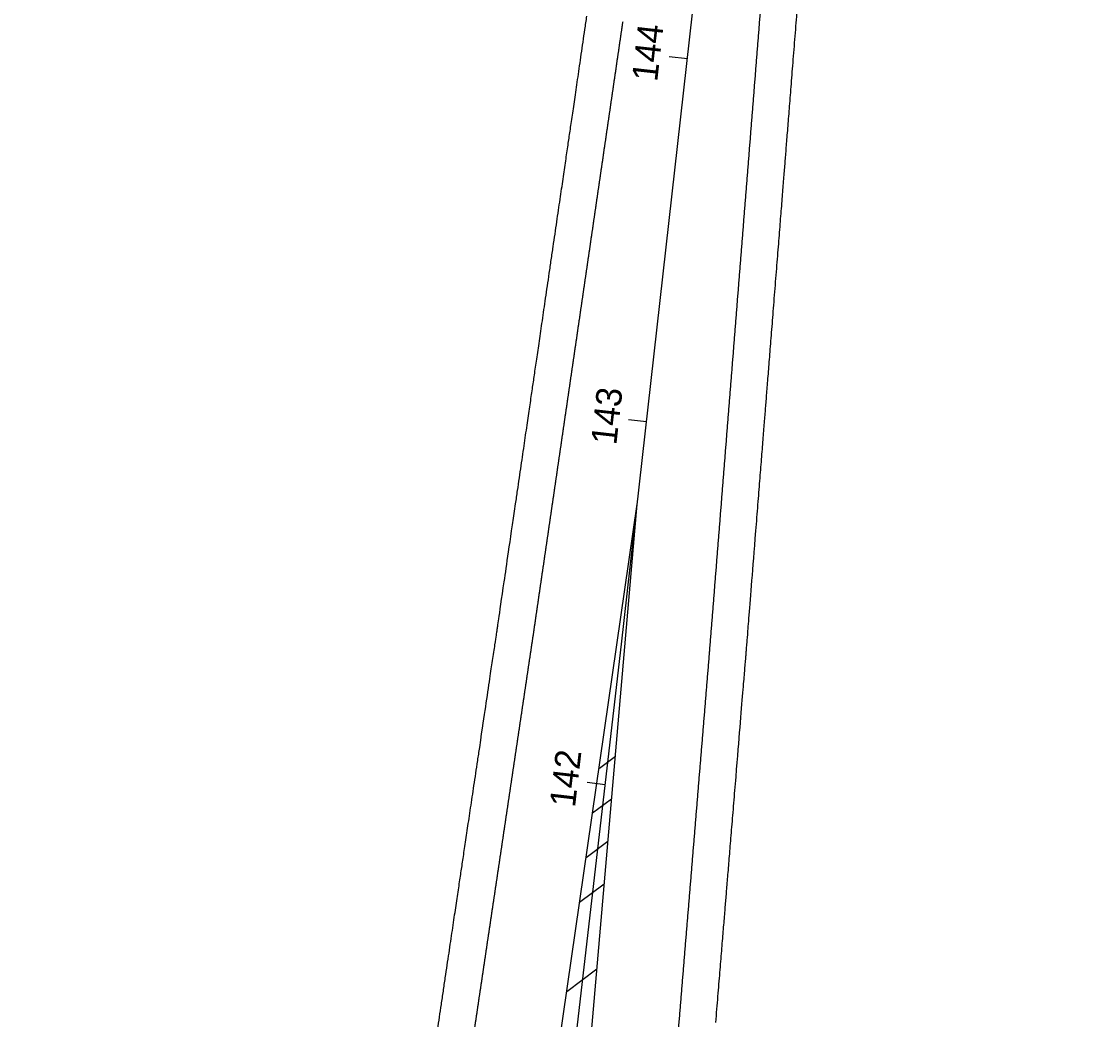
# Model space of a CAD drawing. Extents: x 2318076 to 2324211, y 613525 to 629939.
# Drawn here: x 2320485.2 to 2320778.2, y 628702.1 to 628975.4 of the extents above; entities that cross this region are included whole.
import ezdxf

# ---------------------------------------------------------------- set-up
doc = ezdxf.new("R2010")
doc.units = 0
for name, color, linetype in [('GE_P_CL_50', 7, 'Continuous'), ('PM_P_CL_Double_Solid', 7, 'Continuous'), ('PM_P_Transverse_Line', 7, 'Continuous'), ('PV_P_EOP', 7, 'Continuous'), ('PV_P_Shoulder', 7, 'Continuous')]:
    doc.layers.add(name, color=color, linetype=linetype)

msp = doc.modelspace()

# ---------------------------------------------------------------- linework, layer by layer
at = {"layer": 'GE_P_CL_50'}
for p, q in [((2320667.58, 628965.13), (2320662.61, 628965.69)), ((2320656.38, 628865.76), (2320651.41, 628866.32)), ((2320645.08, 628766.4), (2320640.11, 628766.97))]:
    msp.add_line(p, q, dxfattribs=at)
msp.add_lwpolyline([(2320485.22, 627375.57), (2320502.11, 627520.92), (2320519.22, 627676.47), (2320531.82, 627783.89), (2320546.8, 627927.12), (2320554.45, 627991.34), (2320572.51, 628138.41), (2320649.52, 628804.84), (2320678.77, 629064.5), (2320690.76, 629163.78), (2320713.75, 629362.45), (2320725.26, 629461.78), (2320736.97, 629561.09), (2320748.4, 629660.43), (2320759.09, 629759.86), (2320769.62, 629859.3), (2320777.51, 629931.12), (2320778.25, 629937.84)], dxfattribs=at)
at = {"layer": 'PM_P_CL_Double_Solid'}
for p in [(2320623.21, 628631.42), (2320635.3, 628629.45)]:
    msp.add_line(p, (2320653.84, 628843.21), dxfattribs=at)
at = {"layer": 'PM_P_Transverse_Line'}
for p, q in [((2320647.85, 628774.12), (2320643.47, 628770.85)), ((2320646.84, 628762.47), (2320641.6, 628758.56)), ((2320645.83, 628750.83), (2320639.83, 628746.35)), ((2320644.82, 628739.18), (2320638.07, 628734.13)), ((2320642.8, 628715.89), (2320634.53, 628709.71))]:
    msp.add_line(p, q, dxfattribs=at)
at = {"layer": 'PV_P_EOP'}
for points in [[(2320687.04, 628971.2), (2320687.12, 628972.11), (2320687.19, 628973.02), (2320687.26, 628973.93), (2320687.33, 628974.84), (2320687.4, 628975.75), (2320687.48, 628976.66), (2320687.55, 628977.57), (2320687.62, 628978.48), (2320687.69, 628979.38), (2320687.77, 628980.29), (2320687.84, 628981.2), (2320687.91, 628982.11), (2320687.98, 628983.02), (2320688.05, 628983.93), (2320688.13, 628984.84), (2320688.2, 628985.75), (2320688.27, 628986.66), (2320688.34, 628987.57), (2320688.42, 628988.47), (2320688.49, 628989.38), (2320688.56, 628990.29), (2320688.63, 628991.2), (2320688.7, 628992.11), (2320688.78, 628993.02), (2320688.85, 628993.93), (2320688.92, 628994.84), (2320688.99, 628995.75), (2320689.07, 628996.66), (2320689.14, 628997.57), (2320689.21, 628998.47), (2320689.28, 628999.38), (2320689.35, 629000.29), (2320689.43, 629001.2), (2320689.5, 629002.11), (2320689.57, 629003.02), (2320689.64, 629003.93), (2320689.71, 629004.84), (2320689.79, 629005.75), (2320689.86, 629006.66), (2320689.93, 629007.56), (2320690, 629008.47), (2320690.08, 629009.38), (2320690.15, 629010.29), (2320690.22, 629011.2), (2320690.29, 629012.11), (2320690.36, 629013.02), (2320690.44, 629013.93), (2320690.51, 629014.84), (2320690.58, 629015.75), (2320690.65, 629016.65), (2320690.73, 629017.56), (2320690.8, 629018.47), (2320690.87, 629019.38), (2320690.94, 629020.29), (2320691.01, 629021.2), (2320691.09, 629022.11), (2320691.16, 629023.02), (2320691.23, 629023.93), (2320691.3, 629024.84), (2320691.37, 629025.75), (2320691.45, 629026.65), (2320691.52, 629027.56), (2320691.59, 629028.47), (2320691.66, 629029.38), (2320691.74, 629030.29), (2320691.81, 629031.2), (2320691.88, 629032.11), (2320691.95, 629033.02), (2320692.02, 629033.93), (2320692.1, 629034.84), (2320692.17, 629035.74), (2320692.24, 629036.65), (2320692.31, 629037.56), (2320692.39, 629038.47)], [(2320640.19, 628908.61), (2320640.32, 628909.51), (2320640.45, 628910.41), (2320640.58, 628911.32), (2320640.72, 628912.22), (2320640.85, 628913.12), (2320640.98, 628914.02), (2320641.11, 628914.93), (2320641.24, 628915.83), (2320641.37, 628916.73), (2320641.51, 628917.63), (2320641.64, 628918.54), (2320641.77, 628919.44), (2320641.9, 628920.34), (2320642.03, 628921.24), (2320642.17, 628922.14), (2320642.3, 628923.05), (2320642.43, 628923.95), (2320642.56, 628924.85), (2320642.69, 628925.75), (2320642.82, 628926.66), (2320642.96, 628927.56), (2320643.09, 628928.46), (2320643.22, 628929.36), (2320643.35, 628930.27), (2320643.48, 628931.17), (2320643.62, 628932.07), (2320643.75, 628932.97), (2320643.88, 628933.87), (2320644.01, 628934.78), (2320644.14, 628935.68), (2320644.28, 628936.58), (2320644.41, 628937.48), (2320644.54, 628938.39), (2320644.67, 628939.29), (2320644.8, 628940.19), (2320644.93, 628941.09), (2320645.07, 628942), (2320645.2, 628942.9), (2320645.33, 628943.8), (2320645.46, 628944.7), (2320645.59, 628945.6), (2320645.73, 628946.51), (2320645.86, 628947.41), (2320645.99, 628948.31), (2320646.12, 628949.21), (2320646.25, 628950.12), (2320646.39, 628951.02), (2320646.52, 628951.92), (2320646.65, 628952.82), (2320646.78, 628953.73), (2320646.91, 628954.63), (2320647.04, 628955.53), (2320647.18, 628956.43), (2320647.31, 628957.34), (2320647.44, 628958.24), (2320647.57, 628959.14), (2320647.7, 628960.04), (2320647.84, 628960.94), (2320647.97, 628961.85), (2320648.1, 628962.75), (2320648.23, 628963.65), (2320648.36, 628964.55), (2320648.49, 628965.46), (2320648.63, 628966.36), (2320648.76, 628967.26), (2320648.89, 628968.16), (2320649.02, 628969.07), (2320649.15, 628969.97), (2320649.29, 628970.87), (2320649.42, 628971.77), (2320649.55, 628972.67), (2320649.68, 628973.58), (2320649.81, 628974.48), (2320649.95, 628975.38)], [(2320681.7, 628903.93), (2320681.78, 628904.84), (2320681.85, 628905.75), (2320681.92, 628906.66), (2320681.99, 628907.57), (2320682.06, 628908.48), (2320682.14, 628909.39), (2320682.21, 628910.3), (2320682.28, 628911.21), (2320682.35, 628912.11), (2320682.42, 628913.02), (2320682.5, 628913.93), (2320682.57, 628914.84), (2320682.64, 628915.75), (2320682.71, 628916.66), (2320682.79, 628917.57), (2320682.86, 628918.48), (2320682.93, 628919.39), (2320683, 628920.3), (2320683.07, 628921.21), (2320683.15, 628922.11), (2320683.22, 628923.02), (2320683.29, 628923.93), (2320683.36, 628924.84), (2320683.44, 628925.75), (2320683.51, 628926.66), (2320683.58, 628927.57), (2320683.65, 628928.48), (2320683.72, 628929.39), (2320683.8, 628930.3), (2320683.87, 628931.2), (2320683.94, 628932.11), (2320684.01, 628933.02), (2320684.08, 628933.93), (2320684.16, 628934.84), (2320684.23, 628935.75), (2320684.3, 628936.66), (2320684.37, 628937.57), (2320684.45, 628938.48), (2320684.52, 628939.39), (2320684.59, 628940.3), (2320684.66, 628941.2), (2320684.73, 628942.11), (2320684.81, 628943.02), (2320684.88, 628943.93), (2320684.95, 628944.84), (2320685.02, 628945.75), (2320685.1, 628946.66), (2320685.17, 628947.57), (2320685.24, 628948.48), (2320685.31, 628949.39), (2320685.38, 628950.29), (2320685.46, 628951.2), (2320685.53, 628952.11), (2320685.6, 628953.02), (2320685.67, 628953.93), (2320685.74, 628954.84), (2320685.82, 628955.75), (2320685.89, 628956.66), (2320685.96, 628957.57), (2320686.03, 628958.48), (2320686.11, 628959.39), (2320686.18, 628960.29), (2320686.25, 628961.2), (2320686.32, 628962.11), (2320686.39, 628963.02), (2320686.47, 628963.93), (2320686.54, 628964.84), (2320686.61, 628965.75), (2320686.68, 628966.66), (2320686.76, 628967.57), (2320686.83, 628968.48), (2320686.9, 628969.38), (2320686.97, 628970.29), (2320687.04, 628971.2)], [(2320630.43, 628841.84), (2320630.56, 628842.74), (2320630.69, 628843.64), (2320630.83, 628844.54), (2320630.96, 628845.45), (2320631.09, 628846.35), (2320631.22, 628847.25), (2320631.35, 628848.15), (2320631.49, 628849.06), (2320631.62, 628849.96), (2320631.75, 628850.86), (2320631.88, 628851.76), (2320632.01, 628852.67), (2320632.14, 628853.57), (2320632.28, 628854.47), (2320632.41, 628855.37), (2320632.54, 628856.28), (2320632.67, 628857.18), (2320632.8, 628858.08), (2320632.94, 628858.98), (2320633.07, 628859.88), (2320633.2, 628860.79), (2320633.33, 628861.69), (2320633.46, 628862.59), (2320633.59, 628863.49), (2320633.73, 628864.4), (2320633.86, 628865.3), (2320633.99, 628866.2), (2320634.12, 628867.1), (2320634.25, 628868.01), (2320634.39, 628868.91), (2320634.52, 628869.81), (2320634.65, 628870.71), (2320634.78, 628871.61), (2320634.91, 628872.52), (2320635.05, 628873.42), (2320635.18, 628874.32), (2320635.31, 628875.22), (2320635.44, 628876.13), (2320635.57, 628877.03), (2320635.7, 628877.93), (2320635.84, 628878.83), (2320635.97, 628879.74), (2320636.1, 628880.64), (2320636.23, 628881.54), (2320636.36, 628882.44), (2320636.5, 628883.34), (2320636.63, 628884.25), (2320636.76, 628885.15), (2320636.89, 628886.05), (2320637.02, 628886.95), (2320637.16, 628887.86), (2320637.29, 628888.76), (2320637.42, 628889.66), (2320637.55, 628890.56), (2320637.68, 628891.47), (2320637.81, 628892.37), (2320637.95, 628893.27), (2320638.08, 628894.17), (2320638.21, 628895.07), (2320638.34, 628895.98), (2320638.47, 628896.88), (2320638.61, 628897.78), (2320638.74, 628898.68), (2320638.87, 628899.59), (2320639, 628900.49), (2320639.13, 628901.39), (2320639.26, 628902.29), (2320639.4, 628903.2), (2320639.53, 628904.1), (2320639.66, 628905), (2320639.79, 628905.9), (2320639.92, 628906.81), (2320640.06, 628907.71), (2320640.19, 628908.61)], [(2320676.36, 628836.66), (2320676.43, 628837.57), (2320676.51, 628838.48), (2320676.58, 628839.39), (2320676.65, 628840.3), (2320676.72, 628841.21), (2320676.8, 628842.12), (2320676.87, 628843.03), (2320676.94, 628843.94), (2320677.01, 628844.85), (2320677.08, 628845.75), (2320677.16, 628846.66), (2320677.23, 628847.57), (2320677.3, 628848.48), (2320677.37, 628849.39), (2320677.44, 628850.3), (2320677.52, 628851.21), (2320677.59, 628852.12), (2320677.66, 628853.03), (2320677.73, 628853.94), (2320677.81, 628854.84), (2320677.88, 628855.75), (2320677.95, 628856.66), (2320678.02, 628857.57), (2320678.09, 628858.48), (2320678.17, 628859.39), (2320678.24, 628860.3), (2320678.31, 628861.21), (2320678.38, 628862.12), (2320678.46, 628863.03), (2320678.53, 628863.94), (2320678.6, 628864.84), (2320678.67, 628865.75), (2320678.74, 628866.66), (2320678.82, 628867.57), (2320678.89, 628868.48), (2320678.96, 628869.39), (2320679.03, 628870.3), (2320679.1, 628871.21), (2320679.18, 628872.12), (2320679.25, 628873.03), (2320679.32, 628873.93), (2320679.39, 628874.84), (2320679.47, 628875.75), (2320679.54, 628876.66), (2320679.61, 628877.57), (2320679.68, 628878.48), (2320679.75, 628879.39), (2320679.83, 628880.3), (2320679.9, 628881.21), (2320679.97, 628882.12), (2320680.04, 628883.03), (2320680.12, 628883.93), (2320680.19, 628884.84), (2320680.26, 628885.75), (2320680.33, 628886.66), (2320680.4, 628887.57), (2320680.48, 628888.48), (2320680.55, 628889.39), (2320680.62, 628890.3), (2320680.69, 628891.21), (2320680.76, 628892.12), (2320680.84, 628893.02), (2320680.91, 628893.93), (2320680.98, 628894.84), (2320681.05, 628895.75), (2320681.13, 628896.66), (2320681.2, 628897.57), (2320681.27, 628898.48), (2320681.34, 628899.39), (2320681.41, 628900.3), (2320681.49, 628901.21), (2320681.56, 628902.12), (2320681.63, 628903.02), (2320681.7, 628903.93)], [(2320620.59, 628775.15), (2320620.72, 628776.05), (2320620.86, 628776.95), (2320620.99, 628777.85), (2320621.12, 628778.76), (2320621.26, 628779.66), (2320621.39, 628780.56), (2320621.53, 628781.46), (2320621.66, 628782.36), (2320621.8, 628783.27), (2320621.93, 628784.17), (2320622.07, 628785.07), (2320622.2, 628785.97), (2320622.34, 628786.87), (2320622.47, 628787.78), (2320622.6, 628788.68), (2320622.74, 628789.58), (2320622.87, 628790.48), (2320623.01, 628791.38), (2320623.14, 628792.29), (2320623.28, 628793.19), (2320623.41, 628794.09), (2320623.55, 628794.99), (2320623.68, 628795.89), (2320623.81, 628796.8), (2320623.95, 628797.7), (2320624.08, 628798.6), (2320624.22, 628799.5), (2320624.35, 628800.4), (2320624.49, 628801.31), (2320624.62, 628802.21), (2320624.76, 628803.11), (2320624.89, 628804.01), (2320625.02, 628804.91), (2320625.16, 628805.82), (2320625.29, 628806.72), (2320625.43, 628807.62), (2320625.55, 628808.45), (2320625.68, 628809.35), (2320625.82, 628810.26), (2320625.95, 628811.16), (2320626.08, 628812.06), (2320626.21, 628812.96), (2320626.34, 628813.87), (2320626.47, 628814.77), (2320626.61, 628815.67), (2320626.74, 628816.57), (2320626.87, 628817.48), (2320627, 628818.38), (2320627.13, 628819.28), (2320627.27, 628820.18), (2320627.4, 628821.08), (2320627.53, 628821.99), (2320627.66, 628822.89), (2320627.79, 628823.79), (2320627.92, 628824.69), (2320628.06, 628825.6), (2320628.19, 628826.5), (2320628.32, 628827.4), (2320628.45, 628828.3), (2320628.58, 628829.21), (2320628.72, 628830.11), (2320628.85, 628831.01), (2320628.98, 628831.91), (2320629.11, 628832.81), (2320629.24, 628833.72), (2320629.38, 628834.62), (2320629.51, 628835.52), (2320629.64, 628836.42), (2320629.77, 628837.33), (2320629.9, 628838.23), (2320630.03, 628839.13), (2320630.17, 628840.03), (2320630.3, 628840.94), (2320630.43, 628841.84)], [(2320670.92, 628769.33), (2320670.99, 628770.24), (2320671.07, 628771.15), (2320671.14, 628772.06), (2320671.22, 628772.97), (2320671.29, 628773.88), (2320671.37, 628774.79), (2320671.44, 628775.69), (2320671.52, 628776.6), (2320671.59, 628777.51), (2320671.67, 628778.42), (2320671.74, 628779.33), (2320671.82, 628780.24), (2320671.89, 628781.15), (2320671.97, 628782.06), (2320672.04, 628782.97), (2320672.12, 628783.87), (2320672.19, 628784.78), (2320672.27, 628785.69), (2320672.34, 628786.6), (2320672.41, 628787.51), (2320672.49, 628788.42), (2320672.56, 628789.33), (2320672.64, 628790.24), (2320672.71, 628791.14), (2320672.79, 628792.05), (2320672.86, 628792.96), (2320672.94, 628793.87), (2320673.01, 628794.78), (2320673.09, 628795.69), (2320673.16, 628796.6), (2320673.24, 628797.51), (2320673.31, 628798.42), (2320673.39, 628799.32), (2320673.46, 628800.23), (2320673.54, 628801.14), (2320673.61, 628802.05), (2320673.69, 628803.03), (2320673.76, 628803.94), (2320673.84, 628804.85), (2320673.91, 628805.76), (2320673.98, 628806.67), (2320674.05, 628807.57), (2320674.12, 628808.48), (2320674.2, 628809.39), (2320674.27, 628810.3), (2320674.34, 628811.21), (2320674.41, 628812.12), (2320674.49, 628813.03), (2320674.56, 628813.94), (2320674.63, 628814.85), (2320674.7, 628815.76), (2320674.77, 628816.67), (2320674.85, 628817.57), (2320674.92, 628818.48), (2320674.99, 628819.39), (2320675.06, 628820.3), (2320675.13, 628821.21), (2320675.21, 628822.12), (2320675.28, 628823.03), (2320675.35, 628823.94), (2320675.42, 628824.85), (2320675.5, 628825.76), (2320675.57, 628826.66), (2320675.64, 628827.57), (2320675.71, 628828.48), (2320675.78, 628829.39), (2320675.86, 628830.3), (2320675.93, 628831.21), (2320676, 628832.12), (2320676.07, 628833.03), (2320676.15, 628833.94), (2320676.22, 628834.85), (2320676.29, 628835.75), (2320676.36, 628836.66)], [(2320610.64, 628708.41), (2320610.77, 628709.31), (2320610.91, 628710.21), (2320611.04, 628711.11), (2320611.18, 628712.01), (2320611.31, 628712.92), (2320611.44, 628713.82), (2320611.58, 628714.72), (2320611.71, 628715.62), (2320611.85, 628716.52), (2320611.98, 628717.42), (2320612.12, 628718.33), (2320612.25, 628719.23), (2320612.39, 628720.13), (2320612.52, 628721.03), (2320612.65, 628721.93), (2320612.79, 628722.84), (2320612.92, 628723.74), (2320613.06, 628724.64), (2320613.19, 628725.54), (2320613.33, 628726.44), (2320613.46, 628727.35), (2320613.6, 628728.25), (2320613.73, 628729.15), (2320613.86, 628730.05), (2320614, 628730.95), (2320614.13, 628731.86), (2320614.27, 628732.76), (2320614.4, 628733.66), (2320614.54, 628734.56), (2320614.67, 628735.46), (2320614.81, 628736.37), (2320614.94, 628737.27), (2320615.07, 628738.17), (2320615.21, 628739.07), (2320615.34, 628739.97), (2320615.48, 628740.88), (2320615.61, 628741.78), (2320615.75, 628742.68), (2320615.88, 628743.58), (2320616.02, 628744.48), (2320616.15, 628745.39), (2320616.28, 628746.29), (2320616.42, 628747.19), (2320616.55, 628748.09), (2320616.69, 628748.99), (2320616.82, 628749.89), (2320616.96, 628750.8), (2320617.09, 628751.7), (2320617.23, 628752.6), (2320617.36, 628753.5), (2320617.49, 628754.4), (2320617.63, 628755.31), (2320617.76, 628756.21), (2320617.9, 628757.11), (2320618.03, 628758.01), (2320618.17, 628758.91), (2320618.3, 628759.82), (2320618.44, 628760.72), (2320618.57, 628761.62), (2320618.7, 628762.52), (2320618.84, 628763.42), (2320618.97, 628764.33), (2320619.11, 628765.23), (2320619.24, 628766.13), (2320619.38, 628767.03), (2320619.51, 628767.93), (2320619.65, 628768.84), (2320619.78, 628769.74), (2320619.91, 628770.64), (2320620.05, 628771.54), (2320620.18, 628772.44), (2320620.32, 628773.35), (2320620.45, 628774.25), (2320620.59, 628775.15)], [(2320665.38, 628702.08), (2320665.46, 628702.99), (2320665.53, 628703.9), (2320665.61, 628704.81), (2320665.68, 628705.71), (2320665.76, 628706.62), (2320665.83, 628707.53), (2320665.91, 628708.44), (2320665.98, 628709.35), (2320666.06, 628710.26), (2320666.13, 628711.17), (2320666.21, 628712.08), (2320666.28, 628712.99), (2320666.36, 628713.89), (2320666.43, 628714.8), (2320666.51, 628715.71), (2320666.58, 628716.62), (2320666.66, 628717.53), (2320666.73, 628718.44), (2320666.81, 628719.35), (2320666.88, 628720.26), (2320666.95, 628721.16), (2320667.03, 628722.07), (2320667.1, 628722.98), (2320667.18, 628723.89), (2320667.25, 628724.8), (2320667.33, 628725.71), (2320667.4, 628726.62), (2320667.48, 628727.53), (2320667.55, 628728.44), (2320667.63, 628729.34), (2320667.7, 628730.25), (2320667.78, 628731.16), (2320667.85, 628732.07), (2320667.93, 628732.98), (2320668, 628733.89), (2320668.08, 628734.8), (2320668.15, 628735.71), (2320668.23, 628736.61), (2320668.3, 628737.52), (2320668.38, 628738.43), (2320668.45, 628739.34), (2320668.53, 628740.25), (2320668.6, 628741.16), (2320668.68, 628742.07), (2320668.75, 628742.98), (2320668.82, 628743.89), (2320668.9, 628744.79), (2320668.97, 628745.7), (2320669.05, 628746.61), (2320669.12, 628747.52), (2320669.2, 628748.43), (2320669.27, 628749.34), (2320669.35, 628750.25), (2320669.42, 628751.16), (2320669.5, 628752.07), (2320669.57, 628752.97), (2320669.65, 628753.88), (2320669.72, 628754.79), (2320669.8, 628755.7), (2320669.87, 628756.61), (2320669.95, 628757.52), (2320670.02, 628758.43), (2320670.1, 628759.34), (2320670.17, 628760.24), (2320670.25, 628761.15), (2320670.32, 628762.06), (2320670.4, 628762.97), (2320670.47, 628763.88), (2320670.54, 628764.79), (2320670.62, 628765.7), (2320670.69, 628766.61), (2320670.77, 628767.52), (2320670.84, 628768.42), (2320670.92, 628769.33)], [(2320600.69, 628641.66), (2320600.82, 628642.56), (2320600.96, 628643.47), (2320601.09, 628644.37), (2320601.23, 628645.27), (2320601.36, 628646.17), (2320601.49, 628647.07), (2320601.63, 628647.98), (2320601.76, 628648.88), (2320601.9, 628649.78), (2320602.03, 628650.68), (2320602.17, 628651.58), (2320602.3, 628652.49), (2320602.44, 628653.39), (2320602.57, 628654.29), (2320602.7, 628655.19), (2320602.84, 628656.09), (2320602.97, 628657), (2320603.11, 628657.9), (2320603.24, 628658.8), (2320603.38, 628659.7), (2320603.51, 628660.6), (2320603.65, 628661.5), (2320603.78, 628662.41), (2320603.91, 628663.31), (2320604.05, 628664.21), (2320604.18, 628665.11), (2320604.32, 628666.01), (2320604.45, 628666.92), (2320604.59, 628667.82), (2320604.72, 628668.72), (2320604.86, 628669.62), (2320604.99, 628670.52), (2320605.12, 628671.43), (2320605.26, 628672.33), (2320605.39, 628673.23), (2320605.53, 628674.13), (2320605.66, 628675.03), (2320605.8, 628675.94), (2320605.93, 628676.84), (2320606.07, 628677.74), (2320606.2, 628678.64), (2320606.33, 628679.54), (2320606.47, 628680.45), (2320606.6, 628681.35), (2320606.74, 628682.25), (2320606.87, 628683.15), (2320607.01, 628684.05), (2320607.14, 628684.96), (2320607.28, 628685.86), (2320607.41, 628686.76), (2320607.55, 628687.66), (2320607.68, 628688.56), (2320607.81, 628689.46), (2320607.95, 628690.37), (2320608.08, 628691.27), (2320608.22, 628692.17), (2320608.35, 628693.07), (2320608.49, 628693.97), (2320608.62, 628694.88), (2320608.76, 628695.78), (2320608.89, 628696.68), (2320609.02, 628697.58), (2320609.16, 628698.48), (2320609.29, 628699.39), (2320609.43, 628700.29), (2320609.56, 628701.19), (2320609.7, 628702.09), (2320609.83, 628702.99), (2320609.97, 628703.9), (2320610.1, 628704.8), (2320610.23, 628705.7), (2320610.37, 628706.6), (2320610.5, 628707.5), (2320610.64, 628708.41)], [(2320659.85, 628634.83), (2320659.92, 628635.73), (2320660, 628636.64), (2320660.07, 628637.55), (2320660.15, 628638.46), (2320660.22, 628639.37), (2320660.3, 628640.28), (2320660.37, 628641.19), (2320660.45, 628642.1), (2320660.52, 628643.01), (2320660.6, 628643.91), (2320660.67, 628644.82), (2320660.75, 628645.73), (2320660.82, 628646.64), (2320660.9, 628647.55), (2320660.97, 628648.46), (2320661.05, 628649.37), (2320661.12, 628650.28), (2320661.2, 628651.18), (2320661.27, 628652.09), (2320661.35, 628653), (2320661.42, 628653.91), (2320661.5, 628654.82), (2320661.57, 628655.73), (2320661.64, 628656.64), (2320661.72, 628657.55), (2320661.79, 628658.46), (2320661.87, 628659.36), (2320661.94, 628660.27), (2320662.02, 628661.18), (2320662.09, 628662.09), (2320662.17, 628663), (2320662.24, 628663.91), (2320662.32, 628664.82), (2320662.39, 628665.73), (2320662.47, 628666.63), (2320662.54, 628667.54), (2320662.62, 628668.45), (2320662.69, 628669.36), (2320662.77, 628670.27), (2320662.84, 628671.18), (2320662.92, 628672.09), (2320662.99, 628673), (2320663.07, 628673.91), (2320663.14, 628674.81), (2320663.22, 628675.72), (2320663.29, 628676.63), (2320663.36, 628677.54), (2320663.44, 628678.45), (2320663.51, 628679.36), (2320663.59, 628680.27), (2320663.66, 628681.18), (2320663.74, 628682.08), (2320663.81, 628682.99), (2320663.89, 628683.9), (2320663.96, 628684.81), (2320664.04, 628685.72), (2320664.11, 628686.63), (2320664.19, 628687.54), (2320664.26, 628688.45), (2320664.34, 628689.36), (2320664.41, 628690.26), (2320664.49, 628691.17), (2320664.56, 628692.08), (2320664.64, 628692.99), (2320664.71, 628693.9), (2320664.79, 628694.81), (2320664.86, 628695.72), (2320664.94, 628696.63), (2320665.01, 628697.54), (2320665.09, 628698.44), (2320665.16, 628699.35), (2320665.23, 628700.26), (2320665.31, 628701.17), (2320665.38, 628702.08)]]:
    msp.add_spline(points, degree=3, dxfattribs=at)
at = {"layer": 'PV_P_Shoulder'}
for points, degree in [([(2320697.01, 628970.41), (2320698.79, 628992.83), (2320700.57, 629015.26), (2320702.35, 629037.68)], 2), ([(2320630.29, 628910.06), (2320633.55, 628932.31), (2320636.8, 628954.57), (2320640.05, 628976.83)], 2), ([(2320691.67, 628903.14), (2320693.45, 628925.56), (2320695.23, 628947.99), (2320697.01, 628970.41)], 2), ([(2320620.54, 628843.28), (2320623.79, 628865.54), (2320627.04, 628887.8), (2320630.29, 628910.06)], 2), ([(2320686.33, 628835.87), (2320688.11, 628858.3), (2320689.89, 628880.72), (2320691.67, 628903.14)], 2), ([(2320610.7, 628776.62), (2320611.52, 628782.18), (2320612.35, 628787.73), (2320613.59, 628796.07), (2320614.21, 628800.24), (2320614.94, 628805.11), (2320615.3, 628807.54), (2320615.46, 628808.58), (2320615.54, 628809.1), (2320615.56, 628809.28), (2320615.6, 628809.53), (2320615.62, 628809.65), (2320615.64, 628809.79), (2320615.65, 628809.85), (2320615.65, 628809.88), (2320615.66, 628809.89), (2320615.66, 628809.91), (2320617.28, 628821.04), (2320618.91, 628832.17), (2320620.54, 628843.28)], 3), ([(2320680.89, 628768.51), (2320681.35, 628774.13), (2320682.04, 628782.54), (2320682.84, 628792.36), (2320683.25, 628797.26), (2320683.45, 628799.71), (2320683.54, 628800.76), (2320683.58, 628801.29), (2320683.6, 628801.47), (2320683.63, 628801.83), (2320683.64, 628802.01), (2320683.66, 628802.21), (2320683.66, 628802.22), (2320683.66, 628802.25), (2320683.66, 628802.26), (2320683.66, 628802.29), (2320683.67, 628802.36), (2320683.68, 628802.51), (2320683.71, 628802.82), (2320683.75, 628803.43), (2320683.85, 628804.66), (2320684.05, 628807.11), (2320684.44, 628812.02), (2320685.22, 628821.84), (2320685.89, 628830.26), (2320686.33, 628835.87)], 3), ([(2320600.75, 628709.88), (2320604.06, 628732.13), (2320607.38, 628754.38), (2320610.7, 628776.62)], 2), ([(2320675.35, 628701.26), (2320677.2, 628723.68), (2320679.04, 628746.09), (2320680.89, 628768.51)], 2), ([(2320590.8, 628643.14), (2320594.11, 628665.38), (2320597.43, 628687.63), (2320600.75, 628709.88)], 2)]:
    msp.add_open_spline(points, degree=degree, dxfattribs=at)

# ---------------------------------------------------------------- texts
at = {"layer": 'GE_P_CL_50'}
for s, rotation, p in [('144', 83.5732, (2320659.3, 628958.71)), ('143', 83.5732, (2320648.1, 628859.23)), ('142', 83.4084, (2320636.79, 628759.98))]:
    msp.add_text(s, height=7, rotation=rotation, dxfattribs=at).set_placement(p)

doc.saveas('drawing.dxf')
